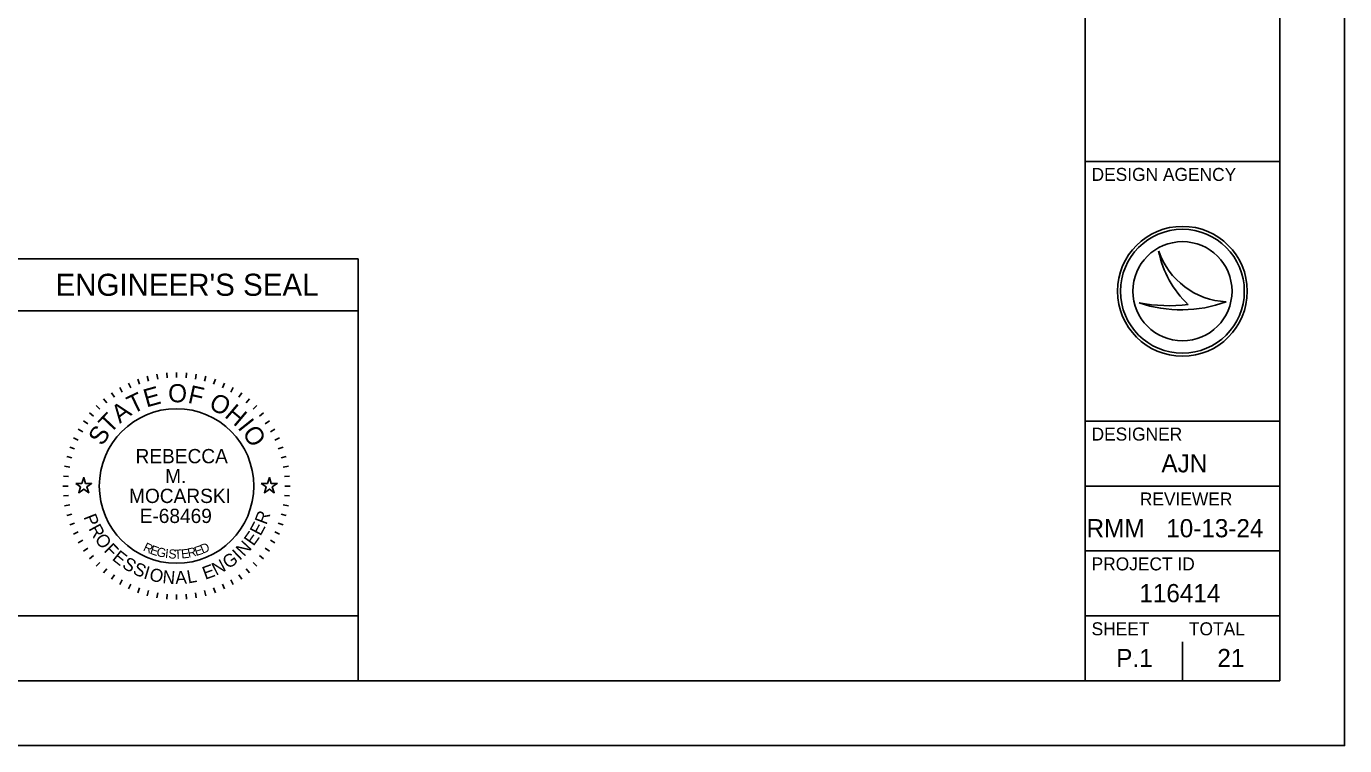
# Model space of a CAD drawing. Extents: x 25.6 to 80.6, y 0.2 to 24.5.
# Drawn here: x 59.36 to 69.51, y 0.23 to 5.77 of the extents above; entities that cross this region are included whole.
import ezdxf

# ---------------------------------------------------------------- set-up
doc = ezdxf.new("R2010")
doc.units = 0
for name, color, linetype in [('Default', 7, 'Continuous'), ('SH_Border', 7, 'Continuous'), ('SH_Cut_Line', 7, 'Continuous'), ('SH_Data', 7, 'Continuous')]:
    doc.layers.add(name, color=color, linetype=linetype)

msp = doc.modelspace()

# ---------------------------------------------------------------- linework, layer by layer
at = {"layer": 'Default'}
for points in [[(59.736, 2.25), (59.783, 2.25), (59.798, 2.295), (59.812, 2.25), (59.859, 2.25), (59.821, 2.223), (59.836, 2.178), (59.798, 2.206), (59.76, 2.178), (59.774, 2.223)], [(61.166, 2.25), (61.213, 2.25), (61.228, 2.295), (61.242, 2.25), (61.289, 2.25), (61.251, 2.223), (61.266, 2.178), (61.228, 2.206), (61.19, 2.178), (61.204, 2.223)]]:
    msp.add_lwpolyline(points, close=True, dxfattribs=at)
at = {"layer": 'SH_Border'}
for p, q in [((67.513, 0.73), (67.513, 21.73)), ((67.513, 4.73), (69.013, 4.73)), ((67.513, 2.73), (69.013, 2.73)), ((67.513, 2.23), (69.013, 2.23)), ((67.513, 1.73), (69.013, 1.73)), ((67.513, 1.23), (69.013, 1.23))]:
    msp.add_line(p, q, dxfattribs=at)
msp.add_lwpolyline([(37.013, 21.73), (69.013, 21.73), (69.013, 0.73), (37.013, 0.73)], close=True, dxfattribs=at)
at = {"layer": 'SH_Cut_Line'}
msp.add_lwpolyline([(35.513, 0.23), (69.513, 0.23), (69.513, 22.23), (35.513, 22.23)], close=True, dxfattribs=at)
at = {"layer": 'SH_Data'}
for p, q in [((59.113, 3.98), (61.913, 3.98)), ((61.913, 3.98), (61.913, 0.73)), ((68.08, 4.04), (68.08, 4.04)), ((68.263, 3.73), (68.263, 3.73)), ((59.113, 3.58), (61.913, 3.58)), ((67.93, 3.64), (67.93, 3.64)), ((68.6, 3.649), (68.6, 3.649)), ((60.214, 3.052), (60.227, 3.015)), ((60.286, 3.075), (60.297, 3.037)), ((60.361, 3.092), (60.368, 3.053)), ((60.437, 3.102), (60.44, 3.062)), ((60.513, 3.105), (60.513, 3.065)), ((60.589, 3.102), (60.586, 3.062)), ((60.665, 3.092), (60.658, 3.053)), ((60.739, 3.075), (60.729, 3.037)), ((60.812, 3.052), (60.798, 3.015)), ((60.011, 2.947), (60.034, 2.914)), ((60.075, 2.988), (60.095, 2.953)), ((60.143, 3.023), (60.16, 2.987)), ((60.883, 3.023), (60.866, 2.987)), ((60.95, 2.988), (60.93, 2.953)), ((61.015, 2.947), (60.992, 2.914)), ((59.894, 2.849), (59.922, 2.821)), ((59.95, 2.901), (59.976, 2.87)), ((61.075, 2.901), (61.05, 2.87)), ((61.132, 2.849), (61.103, 2.821)), ((59.843, 2.793), (59.873, 2.767)), ((61.183, 2.793), (61.152, 2.767)), ((59.755, 2.668), (59.79, 2.648)), ((59.796, 2.732), (59.829, 2.709)), ((61.23, 2.732), (61.197, 2.709)), ((61.271, 2.668), (61.236, 2.648)), ((59.72, 2.6), (59.756, 2.583)), ((61.306, 2.6), (61.27, 2.583)), ((59.668, 2.457), (59.706, 2.446)), ((59.691, 2.53), (59.728, 2.516)), ((61.335, 2.53), (61.297, 2.516)), ((61.358, 2.457), (61.319, 2.446)), ((59.651, 2.382), (59.69, 2.375)), ((61.375, 2.382), (61.335, 2.375)), ((59.641, 2.307), (59.681, 2.303)), ((61.384, 2.307), (61.345, 2.303)), ((59.638, 2.23), (59.678, 2.23)), ((59.641, 2.154), (59.681, 2.157)), ((61.384, 2.154), (61.345, 2.157)), ((61.388, 2.23), (61.348, 2.23)), ((59.651, 2.078), (59.69, 2.085)), ((61.375, 2.078), (61.335, 2.085)), ((59.668, 2.004), (59.706, 2.014)), ((59.691, 1.931), (59.728, 1.945)), ((61.335, 1.931), (61.297, 1.945)), ((61.358, 2.004), (61.319, 2.014)), ((59.72, 1.86), (59.756, 1.877)), ((61.306, 1.86), (61.27, 1.877)), ((59.755, 1.793), (59.79, 1.813)), ((59.796, 1.728), (59.829, 1.751)), ((61.23, 1.728), (61.197, 1.751)), ((61.271, 1.793), (61.236, 1.813)), ((59.843, 1.668), (59.873, 1.694)), ((59.894, 1.612), (59.922, 1.64)), ((61.132, 1.612), (61.103, 1.64)), ((61.183, 1.668), (61.152, 1.694)), ((59.95, 1.56), (59.976, 1.591)), ((60.011, 1.513), (60.034, 1.546)), ((61.015, 1.513), (60.992, 1.546)), ((61.075, 1.56), (61.05, 1.591)), ((60.075, 1.472), (60.095, 1.507)), ((60.143, 1.437), (60.16, 1.473)), ((60.214, 1.408), (60.227, 1.446)), ((60.286, 1.385), (60.297, 1.424)), ((60.739, 1.385), (60.729, 1.424)), ((60.812, 1.408), (60.798, 1.446)), ((60.883, 1.437), (60.866, 1.473)), ((60.95, 1.472), (60.93, 1.507)), ((60.361, 1.369), (60.368, 1.408)), ((60.437, 1.359), (60.44, 1.398)), ((60.513, 1.355), (60.513, 1.395)), ((60.589, 1.359), (60.586, 1.398)), ((60.665, 1.369), (60.658, 1.408)), ((68.263, 0.73), (68.263, 1.03)), ((67.888, 0.905), (67.888, 0.905)), ((59.113, 0.73), (61.913, 0.73))]:
    msp.add_line(p, q, dxfattribs=at)
msp.add_lwpolyline([(59.113, 0.73), (59.113, 1.23), (61.913, 1.23), (61.913, 0.73)], close=True, dxfattribs=at)
for centre, radius in [((68.263, 3.73), 0.5), ((68.263, 3.73), 0.477), ((68.263, 3.73), 0.477), ((68.263, 3.73), 0.382), ((60.513, 2.23), 0.595)]:
    msp.add_circle(centre, radius, dxfattribs=at)
for centre, radius, start, end in [((68.629, 4.228), 0.58, 198.9257, 198.9319), ((68.859, 4.2), 0.796, 191.6379, 191.6421), ((68.629, 4.228), 0.58, 198.9319, 267.1657), ((68.859, 4.2), 0.796, 191.6421, 226.0947), ((68.252, 4.6), 1.013, 251.4576, 290.0832), ((68.161, 4.885), 1.266, 259.4964, 259.4995), ((68.252, 4.6), 1.013, 251.4527, 251.4576), ((68.161, 4.885), 1.266, 259.4995, 276.6672)]:
    msp.add_arc(centre, radius, start, end, dxfattribs=at)

# ---------------------------------------------------------------- texts
for s, height, p in [('DESIGN AGENCY', 0.1, (67.563, 4.58)), ("ENGINEER'S SEAL", 0.17, (59.58, 3.695)), ('DESIGNER', 0.1, (67.563, 2.58)), ('REBECCA', 0.11, (60.197, 2.405)), ('AJN', 0.14, (68.101, 2.335)), ('M.', 0.11, (60.425, 2.252)), ('MOCARSKI', 0.11, (60.147, 2.099)), ('REVIEWER', 0.1, (67.935, 2.08)), ('E-68469', 0.11, (60.229, 1.945)), ('RMM', 0.14, (67.524, 1.835)), ('10-13-24', 0.14, (68.138, 1.835)), ('PROJECT ID', 0.1, (67.563, 1.58)), ('116414', 0.14, (67.931, 1.335)), ('SHEET', 0.1, (67.563, 1.08)), ('TOTAL', 0.1, (68.313, 1.08)), ('P.1', 0.14, (67.753, 0.835)), ('21', 0.14, (68.532, 0.835))]:
    msp.add_text(s, height=height, dxfattribs=at).set_placement(p)
for s, height, rotation, p in [('T', 0.14, 25.7167, (60.174, 2.782)), ('E', 0.14, 15.7571, (60.281, 2.834)), ('O', 0.14, 359.7812, (60.448, 2.875)), ('F', 0.14, 347.4362, (60.594, 2.872)), ('A', 0.14, 36.4747, (60.076, 2.708)), ('O', 0.14, 332.2586, (60.753, 2.832)), ('H', 0.14, 319.9136, (60.876, 2.766)), ('T', 0.14, 46.4344, (60.001, 2.627)), ('I', 0.14, 308.367, (60.979, 2.679)), ('S', 0.14, 57.1924, (59.941, 2.532)), ('O', 0.14, 303.1491, (61.015, 2.639)), ('R', 0.1, 69.2322, (61.205, 1.926)), ('P', 0.1, 291.494, (59.795, 1.992)), ('R', 0.1, 298.7311, (59.832, 1.902)), ('E', 0.1, 61.9951, (61.16, 1.84)), ('O', 0.1, 306.4666, (59.878, 1.819)), ('E', 0.1, 54.758, (61.106, 1.762)), ('F', 0.1, 314.7068, (59.947, 1.729)), ('E', 0.1, 321.4393, (60.011, 1.665)), ('R', 0.07, 334.487, (60.25, 1.735)), ('E', 0.07, 341.04, (60.303, 1.71)), ('G', 0.07, 347.4752, (60.354, 1.692)), ('I', 0.07, 353.7858, (60.422, 1.677)), ('S', 0.07, 356.8926, (60.449, 1.673)), ('T', 0.07, 3.0061, (60.498, 1.669)), ('E', 0.07, 6.0117, (60.552, 1.671)), ('R', 0.07, 11.9184, (60.605, 1.678)), ('E', 0.07, 17.6836, (60.663, 1.69)), ('D', 0.07, 23.3052, (60.714, 1.707)), ('I', 0.1, 43.287, (61, 1.652)), ('N', 0.1, 47.0224, (61.033, 1.681)), ('S', 0.1, 328.6764, (60.087, 1.605)), ('S', 0.1, 335.9134, (60.169, 1.557)), ('E', 0.1, 20.0742, (60.734, 1.507)), ('N', 0.1, 27.3113, (60.817, 1.538)), ('G', 0.1, 35.0469, (60.911, 1.587)), ('I', 0.1, 343.1505, (60.253, 1.52)), ('O', 0.1, 346.8859, (60.297, 1.505)), ('N', 0.1, 355.1261, (60.402, 1.482)), ('A', 0.1, 2.8617, (60.505, 1.474)), ('L', 0.1, 10.0987, (60.602, 1.479))]:
    msp.add_text(s, height=height, rotation=rotation, dxfattribs=at).set_placement(p)

doc.saveas('drawing.dxf')
